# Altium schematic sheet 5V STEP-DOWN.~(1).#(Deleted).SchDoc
size A3; SheetNumber: 10; SheetTotal: 10
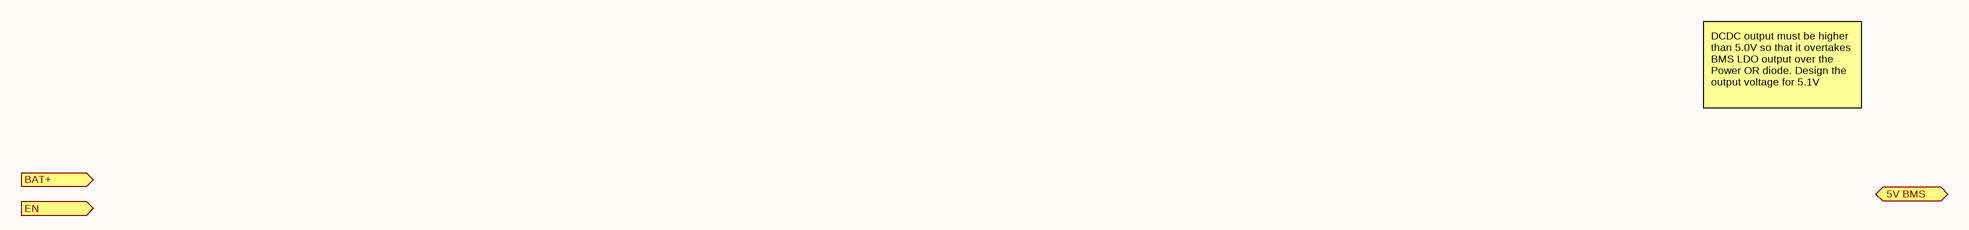
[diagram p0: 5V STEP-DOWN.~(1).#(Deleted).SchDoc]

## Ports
5V BMS (bidir, see BMS[4B]), BAT+ (in, see BMS[4B], BMS[1A], BQ76952 BMS[1A]), EN (in, see BMS[4B])

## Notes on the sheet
- DCDC output must be higher than 5.0V so that it overtakes BMS LDO output over the Power OR diode. Design the output voltage for 5.1V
